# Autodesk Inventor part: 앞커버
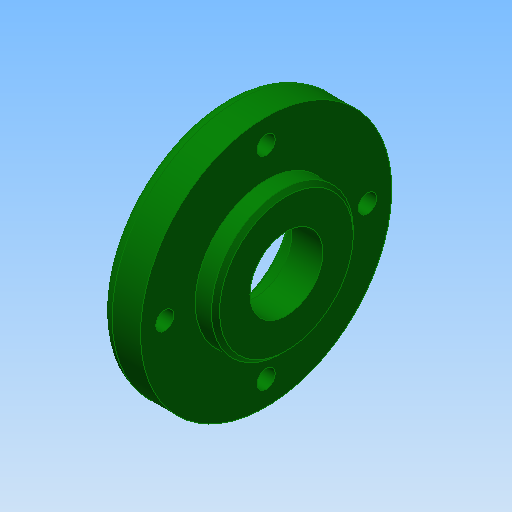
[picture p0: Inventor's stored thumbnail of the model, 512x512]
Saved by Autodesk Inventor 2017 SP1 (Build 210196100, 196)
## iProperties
Created: 2015-12
Part Number: 앞커버
Document SubType Name: Modeling
Designer: mdu
Density: 2.71 g/cm^3
Material: 알루미늄 6061
Appearance: 진녹색
Mass: 70.9292 g
Surface Area: 93.9278 cm^2
Volume: 26.1731 cm^3
Author: mdu
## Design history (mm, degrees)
sketch "스케치1"
  geometry: L1 (-7.5, 0)-(7.5, 0); L2 (-7.5, 0)-(-7.5, 31); L3 (-7.5, 31)-(2.5, 31); L4 (2.5, 31)-(2.5, 17.5); L5 (2.5, 17.5)-(7.5, 17.5); L6 (7.5, 17.5)-(7.5, 0); 2 further points
  constraints: 12 end point, 3 perpendicular, 1 coincident, 1 horizontal, 1 midpoint, 1 parallel
  dimensions: "d0" = 15 distance of L1.start L1.end; "d1" = 62 diameter of L3 L1; "d2" = 35 diameter of L5 L1; "d5" = 10 distance of L2.end L3.end
revolve "회전1" sketch "스케치1" stored, may be unused: angle "d6" = 90 deg
sketch "스케치2" dims "d42" = 50
  geometry: 3 further points
  constraints: 2 vertical alignment, 1 coincident, 2 other
hole "구멍1" sketch "스케치2" at (0, 25) diameter "d8" = 4.5; stored, may be unused: countersink angle "d12" = 90 deg, drill point angle "d14" = 118 deg; dims "d9" = 6, "d10" = 8, "d11" = 4.4, "d13" = 8
hole "구멍2" diameter "d20" = 18; stored, may be unused: countersink angle "d24" = 90 deg, drill point angle "d26" = 0 deg; dims "d18" = 10, "d19" = 10, "d21" = 6, "d22" = 8, "d23" = 4.4, "d25" = 8
hole "구멍3" diameter "d34" = 30; stored, may be unused: countersink angle "d38" = 90 deg, drill point angle "d40" = 0 deg; dims "d32" = 10, "d33" = 10, "d35" = 6, "d36" = 4, "d37" = 2, "d39" = 7.3
fillet "모깎기1" dims "d27" = 3, "d41" = 0.3
chamfer "모따기1" distance "d29" = 1; stored, may be unused: second distance "d30" = 2, angle "d31" = 45 deg
node "솔리드1"
pattern_circular "원형 패턴1" dims angle "d16" = 360 deg
